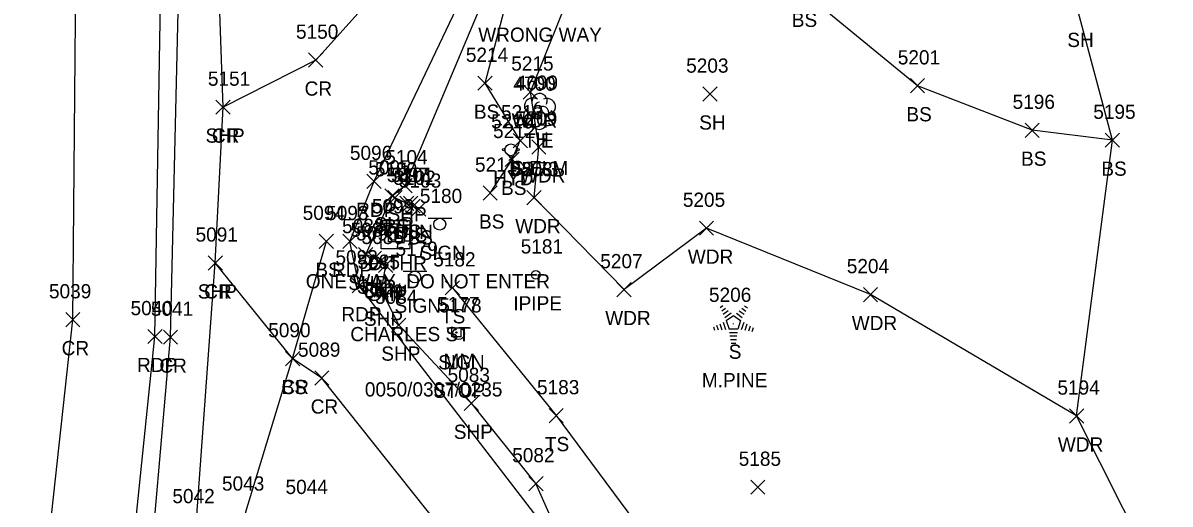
# Model space of a CAD drawing. Extents: x 1769141 to 1770911, y 735471 to 741449.
# Drawn here: x 1770700.3 to 1770861.5, y 739286.9 to 739354.5 of the extents above; entities that cross this region are included whole.
import ezdxf

# ---------------------------------------------------------------- set-up
doc = ezdxf.new("R2010")
doc.units = 0
for name, color, linetype in [('C_A', 7, 'Continuous'), ('C_C', 7, 'Continuous'), ('C_I', 7, 'Continuous'), ('CBP', 7, 'Continuous'), ('D_A', 7, 'Continuous'), ('D_C', 7, 'Continuous'), ('D_I', 7, 'Continuous'), ('D_TIC', 7, 'Continuous'), ('DS', 7, 'Continuous'), ('L_A', 7, 'Continuous'), ('L_C', 7, 'Continuous'), ('L_I', 7, 'Continuous'), ('L_TIC', 7, 'Continuous'), ('LAWA', 7, 'Continuous'), ('LELB', 7, 'Continuous'), ('LSOGP', 7, 'Continuous'), ('LTC', 7, 'Continuous'), ('LTD', 7, 'Continuous'), ('M_A', 7, 'Continuous'), ('M_I', 7, 'Continuous'), ('MPIP', 7, 'Continuous'), ('P_A', 7, 'Continuous'), ('P_I', 7, 'Continuous'), ('P_TIC', 7, 'Continuous'), ('PET', 7, 'Continuous'), ('PRC', 7, 'Continuous'), ('PSP', 7, 'Continuous'), ('S_A', 7, 'Continuous'), ('S_C', 7, 'Continuous'), ('S_I', 7, 'Continuous'), ('SRM', 7, 'Continuous'), ('SSGN', 7, 'Continuous'), ('U_A', 7, 'Continuous'), ('U_I', 7, 'Continuous'), ('UWFH', 7, 'Continuous')]:
    doc.layers.add(name, color=color, linetype=linetype)

msp = doc.modelspace()

# ---------------------------------------------------------------- linework, layer by layer
at = {"layer": 'CBP'}
for radius in [0.625, 0.0833]:
    msp.add_circle((1770772.6, 739342.01), radius, dxfattribs=at)
at = {"layer": 'D_TIC'}
for points in [[(1770753.74, 739328.18), (1770755.74, 739330.18)], [(1770755.74, 739328.18), (1770753.74, 739330.18)], [(1770749.42, 739319.96), (1770751.42, 739321.96)], [(1770751.42, 739319.96), (1770749.42, 739321.96)]]:
    msp.add_lwpolyline(points, dxfattribs=at)
at = {"layer": 'DS'}
for p, q in [((1770750.62, 739326.79), (1770754.62, 739326.79)), ((1770750.62, 739322.79), (1770750.63, 739326.79)), ((1770754.62, 739326.79), (1770754.62, 739322.79)), ((1770751.62, 739325.79), (1770753.62, 739325.79)), ((1770751.62, 739323.79), (1770751.62, 739325.79)), ((1770753.62, 739325.79), (1770753.62, 739323.79)), ((1770753.62, 739323.79), (1770751.62, 739323.79)), ((1770752.62, 739324.8), (1770752.62, 739324.8)), ((1770754.62, 739322.79), (1770750.62, 739322.79)), ((1770753.12, 739322.79), (1770753.62, 739322.79))]:
    msp.add_line(p, q, dxfattribs=at)
at = {"layer": 'L_TIC'}
for points in [[(1770764.2, 739345.07), (1770766.2, 739347.07)], [(1770766.2, 739345.07), (1770764.2, 739347.07)], [(1770770.58, 739343.84), (1770772.58, 739345.84)], [(1770772.58, 739343.84), (1770770.58, 739345.84)], [(1770824.99, 739344.71), (1770826.99, 739346.71)], [(1770826.99, 739344.71), (1770824.99, 739346.71)], [(1770795.82, 739343.55), (1770797.82, 739345.55)], [(1770797.82, 739343.55), (1770795.82, 739345.55)], [(1770841.11, 739338.46), (1770843.11, 739340.46)], [(1770843.11, 739338.46), (1770841.11, 739340.46)], [(1770769.15, 739337), (1770771.15, 739339)], [(1770771.15, 739337), (1770769.15, 739339)], [(1770771.76, 739336.11), (1770773.76, 739338.11)], [(1770773.76, 739336.11), (1770771.76, 739338.11)], [(1770852.39, 739337.06), (1770854.39, 739339.06)], [(1770854.39, 739337.06), (1770852.39, 739339.06)], [(1770768.02, 739334.36), (1770770.02, 739336.36)], [(1770770.02, 739334.36), (1770768.02, 739336.36)], [(1770764.92, 739329.63), (1770766.92, 739331.63)], [(1770766.92, 739329.63), (1770764.92, 739331.63)], [(1770751.56, 739328.98), (1770753.56, 739330.98)], [(1770753.56, 739328.98), (1770751.56, 739330.98)], [(1770753.21, 739328.2), (1770755.21, 739330.2)], [(1770755.21, 739328.2), (1770753.21, 739330.2)], [(1770754.09, 739327.78), (1770756.09, 739329.78)], [(1770756.09, 739327.78), (1770754.09, 739329.78)], [(1770771.09, 739328.99), (1770773.09, 739330.99)], [(1770773.09, 739328.99), (1770771.09, 739330.99)], [(1770754.87, 739327.39), (1770756.87, 739329.39)], [(1770756.87, 739327.39), (1770754.87, 739329.39)], [(1770795.34, 739324.69), (1770797.34, 739326.69)], [(1770797.34, 739324.69), (1770795.34, 739326.69)], [(1770741.91, 739322.85), (1770743.91, 739324.85)], [(1770743.91, 739322.85), (1770741.91, 739324.85)], [(1770759.61, 739316.31), (1770761.61, 739318.31)], [(1770761.61, 739316.31), (1770759.61, 739318.31)], [(1770783.74, 739316.06), (1770785.74, 739318.06)], [(1770785.74, 739316.06), (1770783.74, 739318.06)], [(1770818.39, 739315.36), (1770820.39, 739317.36)], [(1770820.39, 739315.36), (1770818.39, 739317.36)], [(1770737.16, 739306.36), (1770739.16, 739308.36)], [(1770739.16, 739306.36), (1770737.16, 739308.36)], [(1770774.21, 739298.34), (1770776.21, 739300.34)], [(1770776.21, 739298.34), (1770774.21, 739300.34)], [(1770847.36, 739298.29), (1770849.36, 739300.29)], [(1770849.36, 739298.29), (1770847.36, 739300.29)], [(1770802.55, 739288.28), (1770804.55, 739290.28)], [(1770804.55, 739288.28), (1770802.55, 739290.28)]]:
    msp.add_lwpolyline(points, dxfattribs=at)
at = {"layer": 'LAWA'}
msp.add_lwpolyline([(1770848.36, 739299.29), (1770819.39, 739316.36), (1770796.34, 739325.69), (1770784.74, 739317.06), (1770772.09, 739329.99), (1770772.76, 739337.11), (1770771.58, 739344.84), (1770780.05, 739365.89), (1770784.26, 739398.35), (1770789.18, 739434.08), (1770793.15, 739450.42), (1770787.55, 739460.71), (1770784.38, 739492.83), (1770781.25, 739542.67), (1770782.94, 739547.81), (1770785.04, 739555.61), (1770781.08, 739568.95)], dxfattribs=at)
at = {"layer": 'LELB'}
for points in [[(1770853.39, 739338.06), (1770842.11, 739339.46), (1770825.99, 739345.71), (1770809.88, 739358.98), (1770809.92, 739372.24), (1770808.4, 739407.47), (1770798.68, 739434.48), (1770793.15, 739450.42), (1770784.37, 739450.36)], [(1770765.92, 739330.63), (1770769.02, 739335.36), (1770770.15, 739338), (1770765.2, 739346.07), (1770769, 739360.63)], [(1770752.56, 739329.98), (1770754.21, 739329.2), (1770755.09, 739328.78), (1770755.87, 739328.39)], [(1770712.7, 739204.55), (1770718.68, 739230.28), (1770725.15, 739258.34), (1770730.97, 739271.75), (1770731.67, 739275.36), (1770731.57, 739285.8), (1770738.16, 739307.36), (1770742.91, 739323.85)], [(1770760.61, 739317.31), (1770775.21, 739299.34), (1770790.24, 739279.07), (1770818.42, 739252.02), (1770834.29, 739248.48), (1770840.27, 739254.85)]]:
    msp.add_lwpolyline(points, dxfattribs=at)
at = {"layer": 'LSOGP'}
msp.add_lwpolyline([(1770861.49, 739273.14), (1770848.36, 739299.29), (1770853.39, 739338.06), (1770848.56, 739356.16), (1770838.67, 739365.37), (1770833.3, 739374.63), (1770832.51, 739381.01), (1770820.5, 739409.2), (1770815.62, 739419.37), (1770810.36, 739434.31), (1770818.4, 739446.37), (1770815.75, 739456.36), (1770815.75, 739477.85), (1770810.87, 739501.85)], dxfattribs=at)
at = {"layer": 'LTC'}
for p, q in [((1770798.27, 739314.54), (1770798.62, 739314.8)), ((1770798.48, 739314.08), (1770799.01, 739314.46)), ((1770798.69, 739313.61), (1770799.39, 739314.12)), ((1770798.9, 739313.14), (1770799.78, 739313.78)), ((1770800.55, 739313.74), (1770801.36, 739313.15)), ((1770800.93, 739314.09), (1770801.61, 739313.59)), ((1770801.3, 739314.43), (1770801.85, 739314.03)), ((1770801.67, 739314.78), (1770802.09, 739314.48)), ((1770797.76, 739312.04), (1770797.97, 739311.39)), ((1770798.21, 739312.25), (1770798.48, 739311.42)), ((1770798.67, 739312.47), (1770799, 739311.45)), ((1770799.12, 739312.69), (1770800.13, 739313.42)), ((1770799.12, 739312.69), (1770799.51, 739311.5)), ((1770800.13, 739313.42), (1770801.13, 739312.7)), ((1770801.13, 739312.7), (1770800.74, 739311.5)), ((1770801.57, 739312.43), (1770801.23, 739311.39)), ((1770802.01, 739312.18), (1770801.73, 739311.29)), ((1770802.46, 739311.93), (1770802.22, 739311.2)), ((1770797.3, 739311.82), (1770797.45, 739311.35)), ((1770800.74, 739311.5), (1770799.51, 739311.5)), ((1770800.7, 739311), (1770799.56, 739311)), ((1770800.62, 739310.5), (1770799.63, 739310.5)), ((1770802.9, 739311.68), (1770802.72, 739311.1)), ((1770800.53, 739310), (1770799.7, 739310)), ((1770800.45, 739309.5), (1770799.78, 739309.5))]:
    msp.add_line(p, q, dxfattribs=at)
at = {"layer": 'LTD'}
msp.add_line((1770772.83, 739342.15), (1770772.83, 739342.15), dxfattribs=at)
msp.add_line((1770772.83, 739342.15), (1770772.83, 739342.15), dxfattribs=at)
msp.add_arc((1770772.88, 739343.58), 1.05, 335.5272, 180.9563, dxfattribs=at)
for centre, major_axis, ratio, start_param, end_param in [((1770772.04, 739342.81), (1.21, -0.51), 0.895232, 1.570796, 4.712389), ((1770772.63, 739342.6), (-0.208, -0.792), 0.645439, 3.141593, 6.283185), ((1770773.33, 739341.98), (-0.5, 0.667), 0.989748, 3.141593, 6.283185), ((1770773.88, 739342.73), (-1.14, -0.48), 0.949671, 1.570796, 4.712389), ((1770771.75, 739341.44), (0.58, -1.04), 0.959034, 3.141593, 6.283185), ((1770772.38, 739341.4), (-0.625, -0.083), 0.423636, 0, 3.141593), ((1770773.83, 739341.31), (-1.09, 0.79), 0.841452, 1.570796, 4.712389), ((1770772.83, 739340.65), (0.26, 1.06), 0.942809, 1.570796, 4.712389)]:
    msp.add_ellipse(centre, major_axis=major_axis, ratio=ratio, start_param=start_param, end_param=end_param, dxfattribs=at)
at = {"layer": 'MPIP'}
for radius in [0.625, 0.0833]:
    msp.add_circle((1770772.34, 739319.13), radius, dxfattribs=at)
at = {"layer": 'P_TIC'}
for points in [[(1770740.41, 739348.32), (1770742.41, 739350.32)], [(1770742.41, 739348.32), (1770740.41, 739350.32)], [(1770727.38, 739341.71), (1770729.38, 739343.71)], [(1770729.38, 739341.71), (1770727.38, 739343.71)], [(1770727.38, 739341.71), (1770729.38, 739343.71)], [(1770729.38, 739341.71), (1770727.38, 739343.71)], [(1770748.6, 739331.28), (1770750.6, 739333.28)], [(1770750.6, 739331.28), (1770748.6, 739333.28)], [(1770752.96, 739330.67), (1770754.96, 739332.67)], [(1770754.96, 739330.67), (1770752.96, 739332.67)], [(1770751.14, 739329.24), (1770753.14, 739331.24)], [(1770753.14, 739329.24), (1770751.14, 739331.24)], [(1770745.21, 739322.83), (1770747.21, 739324.83)], [(1770747.21, 739322.83), (1770745.21, 739324.83)], [(1770726.29, 739319.8), (1770728.29, 739321.8)], [(1770728.29, 739319.8), (1770726.29, 739321.8)], [(1770726.29, 739319.8), (1770728.29, 739321.8)], [(1770728.29, 739319.8), (1770726.29, 739321.8)], [(1770747.44, 739320.99), (1770749.44, 739322.99)], [(1770749.44, 739320.99), (1770747.44, 739322.99)], [(1770748.65, 739320.47), (1770750.65, 739322.47)], [(1770750.65, 739320.47), (1770748.65, 739322.47)], [(1770750.24, 739319.46), (1770752.24, 739321.46)], [(1770752.24, 739319.46), (1770750.24, 739321.46)], [(1770746.52, 739316.6), (1770748.52, 739318.6)], [(1770748.52, 739316.6), (1770746.52, 739318.6)], [(1770749.64, 739315.97), (1770751.64, 739317.97)], [(1770751.64, 739315.97), (1770749.64, 739317.97)], [(1770706.26, 739311.83), (1770708.26, 739313.83)], [(1770708.26, 739311.83), (1770706.26, 739313.83)], [(1770752.08, 739311.06), (1770754.08, 739313.06)], [(1770754.08, 739311.06), (1770752.08, 739313.06)], [(1770717.8, 739309.46), (1770719.8, 739311.46)], [(1770719.8, 739309.46), (1770717.8, 739311.46)], [(1770720, 739309.37), (1770722, 739311.37)], [(1770722, 739309.37), (1770720, 739311.37)], [(1770737.16, 739306.36), (1770739.16, 739308.36)], [(1770739.16, 739306.36), (1770737.16, 739308.36)], [(1770741.27, 739303.62), (1770743.27, 739305.62)], [(1770743.27, 739303.62), (1770741.27, 739305.62)], [(1770762.28, 739300.07), (1770764.28, 739302.07)], [(1770764.28, 739300.07), (1770762.28, 739302.07)], [(1770771.36, 739288.78), (1770773.36, 739290.78)], [(1770773.36, 739288.78), (1770771.36, 739290.78)]]:
    msp.add_lwpolyline(points, dxfattribs=at)
at = {"layer": 'PET'}
for points in [[(1770664.31, 738997.45), (1770673.48, 739046.36), (1770688.31, 739123.12), (1770698.56, 739176.19), (1770703.43, 739201.32), (1770708.53, 739230.07), (1770714.77, 739271.31), (1770718.8, 739310.46), (1770719.91, 739376.99), (1770716.57, 739419.69), (1770708.47, 739465.39), (1770696.42, 739509.78), (1770680.97, 739557.62), (1770661.26, 739610.33), (1770641.75, 739663.52), (1770622.18, 739716), (1770602.15, 739769.89), (1770585.74, 739814.52), (1770568.14, 739861.61), (1770553.27, 739901.7), (1770537.83, 739943.38)], [(1770826.12, 739215.62), (1770808.71, 739238.73), (1770793.69, 739255.36), (1770777.1, 739279.15), (1770747.52, 739317.6), (1770746.21, 739323.83), (1770749.6, 739332.28), (1770764.58, 739363.7), (1770773.77, 739402.23), (1770777.46, 739441.59), (1770775.37, 739483.39), (1770773.97, 739524.69), (1770772.74, 739572.79)]]:
    msp.add_lwpolyline(points, dxfattribs=at)
at = {"layer": 'PRC'}
for points in [[(1770652.79, 739000.55), (1770661.76, 739049.09), (1770676.76, 739126.68), (1770686.63, 739178.09), (1770691.58, 739203.99), (1770696.85, 739232.92), (1770702.89, 739272.83), (1770707.26, 739312.83), (1770707.84, 739376.22), (1770704.25, 739418.4), (1770696.6, 739463.84), (1770684.34, 739507.25), (1770668.92, 739555.36), (1770649.82, 739606.94), (1770630.97, 739657.66), (1770610.69, 739712.41), (1770591.34, 739764.72), (1770574.45, 739810.22), (1770556.28, 739859.56), (1770544.53, 739890.8), (1770526.88, 739938.69)], [(1770765.46, 739577.52), (1770766.25, 739541.4), (1770766.22, 739502.8), (1770766.86, 739467.3), (1770767.1, 739426.29), (1770764.63, 739394.28), (1770755.81, 739365.32), (1770741.41, 739349.32), (1770728.38, 739342.71)], [(1770697.1, 739152.91), (1770703.6, 739187.83), (1770710.77, 739229.65), (1770717.49, 739270.05), (1770721, 739310.37), (1770722.67, 739382.07)], [(1770817.34, 739209.45), (1770798.63, 739232.87), (1770785.92, 739249.6), (1770767.83, 739272.46), (1770742.27, 739304.62), (1770738.16, 739307.36), (1770727.29, 739320.8)]]:
    msp.add_lwpolyline(points, dxfattribs=at)
at = {"layer": 'PSP'}
for points in [[(1770777.1, 739279.15), (1770772.36, 739289.78), (1770763.28, 739301.07), (1770753.08, 739312.06), (1770750.64, 739316.97), (1770751.24, 739320.46), (1770749.65, 739321.47), (1770748.44, 739321.99), (1770752.14, 739330.24), (1770753.96, 739331.67), (1770766.54, 739361.54), (1770776.63, 739402.31), (1770780.9, 739440.8), (1770778.84, 739483.4), (1770777.57, 739524.87), (1770775.93, 739572.48), (1770777.8, 739574.14), (1770778.96, 739574.79), (1770778.9, 739578.76)], [(1770673.18, 739030.96), (1770682.05, 739077.34), (1770692.5, 739120.97), (1770695.45, 739130.2), (1770697.63, 739138.45), (1770705.03, 739174.85), (1770710.86, 739199.97), (1770715.93, 739228.68), (1770722.76, 739270.72), (1770724.6, 739284.03), (1770727.29, 739320.8), (1770728.38, 739342.71), (1770726.96, 739384.23), (1770723.73, 739420.13), (1770715.24, 739467.3), (1770704.32, 739510.94), (1770687.59, 739558.7)]]:
    msp.add_lwpolyline(points, dxfattribs=at)
at = {"layer": 'SRM'}
msp.add_lwpolyline([(1770760.55, 739311.66), (1770761.8, 739311.66), (1770761.8, 739310.41), (1770760.55, 739310.41)], close=True, dxfattribs=at)
msp.add_circle((1770761.18, 739311.03), 0.0833, dxfattribs=at)
at = {"layer": 'SSGN'}
for p, q in [((1770757.19, 739327.08), (1770760.53, 739327.08)), ((1770758.84, 739326.25), (1770758.84, 739326.25)), ((1770753.69, 739319.66), (1770757.03, 739319.66)), ((1770755.34, 739318.82), (1770755.34, 739318.82)), ((1770759.83, 739311.7), (1770763.17, 739311.7)), ((1770761.48, 739310.86), (1770761.48, 739310.86))]:
    msp.add_line(p, q, dxfattribs=at)
for centre in [(1770758.84, 739326.25), (1770755.34, 739318.82), (1770761.48, 739310.86)]:
    msp.add_circle(centre, 0.833, dxfattribs=at)
at = {"layer": 'UWFH'}
msp.add_line((1770768.84, 739336.71), (1770768.84, 739336.71), dxfattribs=at)
for centre, radius in [((1770767.84, 739336.71), 0.167), ((1770768.84, 739336.71), 0.833), ((1770769.84, 739336.71), 0.167), ((1770768.84, 739335.71), 0.167)]:
    msp.add_circle(centre, radius, dxfattribs=at)

# ---------------------------------------------------------------- texts
at = {"layer": 'C_A'}
msp.add_text('TIE', height=2, dxfattribs=at).set_placement((1770770.68, 739337.01))
at = {"layer": 'C_C'}
msp.add_text('55.73', height=2, dxfattribs=at).set_placement((1770768.85, 739333.01))
at = {"layer": 'C_I'}
msp.add_text('4700', height=2, dxfattribs=at).set_placement((1770769.18, 739345.01))
at = {"layer": 'D_A'}
for s, p in [('DIIN', (1770752.51, 739324.18)), ('DITHR', (1770748.87, 739319.77)), ('DIIN', (1770748.19, 739315.96))]:
    msp.add_text(s, height=2, dxfattribs=at).set_placement(p)
at = {"layer": 'D_C'}
msp.add_text("6'x 9'", height=2, dxfattribs=at).set_placement((1770748.16, 739315.77))
at = {"layer": 'D_I'}
for s, p in [('5097', (1770751.4, 739332.18)), ('5099', (1770749.29, 739327.77)), ('5098', (1770747.08, 739323.96))]:
    msp.add_text(s, height=2, dxfattribs=at).set_placement(p)
at = {"layer": 'L_A'}
for s, p in [('BS', (1770808.32, 739353.98)), ('SH', (1770847.05, 739351.16)), ('BS', (1770763.64, 739341.07)), ('BS', (1770824.43, 739340.71)), ('WDR', (1770768.94, 739339.84)), ('SH', (1770795.31, 739339.55)), ('H', (1770772.27, 739337.15)), ('BS', (1770840.55, 739334.46)), ('BS', (1770768.59, 739333)), ('BS', (1770851.83, 739333.06)), ('WDR', (1770770.12, 739332.11)), ('BS', (1770767.46, 739330.36)), ('BS', (1770751.01, 739324.98)), ('BS', (1770764.36, 739325.63)), ('WDR', (1770769.45, 739324.99)), ('BS', (1770752.65, 739324.2)), ('BS', (1770753.53, 739323.78)), ('BS', (1770754.31, 739323.39)), ('WDR', (1770793.71, 739320.69)), ('BS', (1770741.35, 739318.85)), ('TS', (1770759.02, 739312.31)), ('WDR', (1770782.1, 739312.06)), ('WDR', (1770816.75, 739311.36)), ('S', (1770799.46, 739307.33)), ('BS', (1770736.6, 739302.36)), ('TS', (1770773.62, 739294.34)), ('WDR', (1770845.72, 739294.29))]:
    msp.add_text(s, height=2, dxfattribs=at).set_placement(p)
at = {"layer": 'L_C'}
for s, p in [('S.ELM', (1770768.87, 739333.15)), ('M.PINE', (1770795.68, 739303.33))]:
    msp.add_text(s, height=2, dxfattribs=at).set_placement(p)
at = {"layer": 'L_I'}
for s, p in [('5214', (1770762.51, 739349.07)), ('5201', (1770823.22, 739348.71)), ('5215', (1770768.89, 739347.84)), ('5203', (1770793.48, 739347.55)), ('4699', (1770769.52, 739345.15)), ('5196', (1770839.36, 739342.46)), ('5213', (1770767.45, 739341)), ('5195', (1770850.7, 739341.06)), ('5209', (1770769.41, 739340.11)), ('5212', (1770766.33, 739338.36)), ('5100', (1770749.71, 739332.98)), ('5211', (1770763.79, 739333.63)), ('5208', (1770768.75, 739332.99)), ('5101', (1770752, 739332.2)), ('5102', (1770752.32, 739331.78)), ('5103', (1770753.1, 739331.39)), ('5205', (1770793.01, 739328.69)), ('5094', (1770739.57, 739326.85)), ('5182', (1770757.92, 739320.31)), ('5207', (1770781.4, 739320.06)), ('5204', (1770816.05, 739319.36)), ('5206', (1770796.68, 739315.33)), ('5090', (1770734.73, 739310.36)), ('5183', (1770772.51, 739302.34)), ('5194', (1770845.66, 739302.29)), ('5185', (1770800.86, 739292.28)), ('5043', (1770728.23, 739288.8))]:
    msp.add_text(s, height=2, dxfattribs=at).set_placement(p)
at = {"layer": 'LTC'}
msp.add_text('.', height=1.04, rotation=270, dxfattribs=at).set_placement((1770800.02, 739312.44))
at = {"layer": 'M_A'}
msp.add_text('IPIPE', height=2, dxfattribs=at).set_placement((1770769.18, 739314.13))
at = {"layer": 'M_I'}
msp.add_text('5181', height=2, dxfattribs=at).set_placement((1770770.22, 739322.13))
at = {"layer": 'P_A'}
for s, p in [('CR', (1770739.84, 739344.32)), ('SHP', (1770725.92, 739337.71)), ('CR', (1770726.81, 739337.71)), ('RDP', (1770747.09, 739327.28)), ('SHP', (1770751.5, 739326.67)), ('SHP', (1770749.67, 739325.24)), ('RDP', (1770743.69, 739318.83)), ('SHP', (1770745.98, 739316.99)), ('SHP', (1770747.18, 739316.47)), ('SHP', (1770724.83, 739315.8)), ('CR', (1770725.73, 739315.8)), ('SHP', (1770748.77, 739315.46)), ('RDP', (1770745.01, 739312.6)), ('SHP', (1770748.18, 739311.97)), ('CR', (1770705.69, 739307.83)), ('SHP', (1770750.62, 739307.06)), ('RDP', (1770716.29, 739305.46)), ('CR', (1770719.43, 739305.37)), ('CR', (1770736.59, 739302.36)), ('CR', (1770740.7, 739299.62)), ('SHP', (1770760.81, 739296.07))]:
    msp.add_text(s, height=2, dxfattribs=at).set_placement(p)
at = {"layer": 'P_I'}
for s, p in [('5150', (1770738.63, 739352.32)), ('5151', (1770726.25, 739345.71)), ('5151', (1770726.25, 739345.71)), ('5096', (1770746.21, 739335.28)), ('5104', (1770751.19, 739334.67)), ('5095', (1770748.8, 739333.24)), ('5093', (1770742.87, 739326.83)), ('5088', (1770745.11, 739324.99)), ('5087', (1770746.31, 739324.47)), ('5091', (1770724.52, 739323.8)), ('5091', (1770724.52, 739323.8)), ('5086', (1770747.84, 739323.46)), ('5092', (1770744.18, 739320.6)), ('5085', (1770747.3, 739319.97)), ('5039', (1770703.91, 739315.83)), ('5084', (1770749.75, 739315.06)), ('5040', (1770715.38, 739313.46)), ('5041', (1770718.23, 739313.37)), ('5090', (1770734.73, 739310.36)), ('5089', (1770738.92, 739307.62)), ('5083', (1770759.94, 739304.07)), ('5082', (1770769.02, 739292.78)), ('5043', (1770728.23, 739288.8)), ('5044', (1770737.16, 739288.32)), ('5042', (1770721.26, 739287.03)), ('5042', (1770721.26, 739287.03))]:
    msp.add_text(s, height=2, dxfattribs=at).set_placement(p)
at = {"layer": 'S_A'}
for s, p in [('SIGN', (1770755.98, 739321.23)), ('SIGN', (1770752.48, 739313.8)), ('SIGN', (1770758.62, 739305.84)), ('MM', (1770759.37, 739306.03))]:
    msp.add_text(s, height=2, dxfattribs=at).set_placement(p)
at = {"layer": 'S_C'}
for s, p in [('WRONG WAY', (1770764.25, 739351.89)), ('ONE WAY..DO NOT ENTER', (1770740.01, 739317.23)), ('CHARLES ST', (1770746.27, 739309.8)), ('0050/0307/0235', (1770748.31, 739302.03)), ('STOP', (1770757.94, 739301.84))]:
    msp.add_text(s, height=2, dxfattribs=at).set_placement(p)
at = {"layer": 'S_I'}
for s, p in [('5180', (1770756.04, 739329.23)), ('5179', (1770752.62, 739321.8)), ('5177', (1770758.48, 739314.03)), ('5178', (1770758.77, 739313.84))]:
    msp.add_text(s, height=2, dxfattribs=at).set_placement(p)
at = {"layer": 'U_A'}
msp.add_text('HYD', height=2, dxfattribs=at).set_placement((1770766.36, 739331.71))
at = {"layer": 'U_I'}
msp.add_text('5210', height=2, dxfattribs=at).set_placement((1770766.06, 739339.71))

doc.saveas('drawing.dxf')
